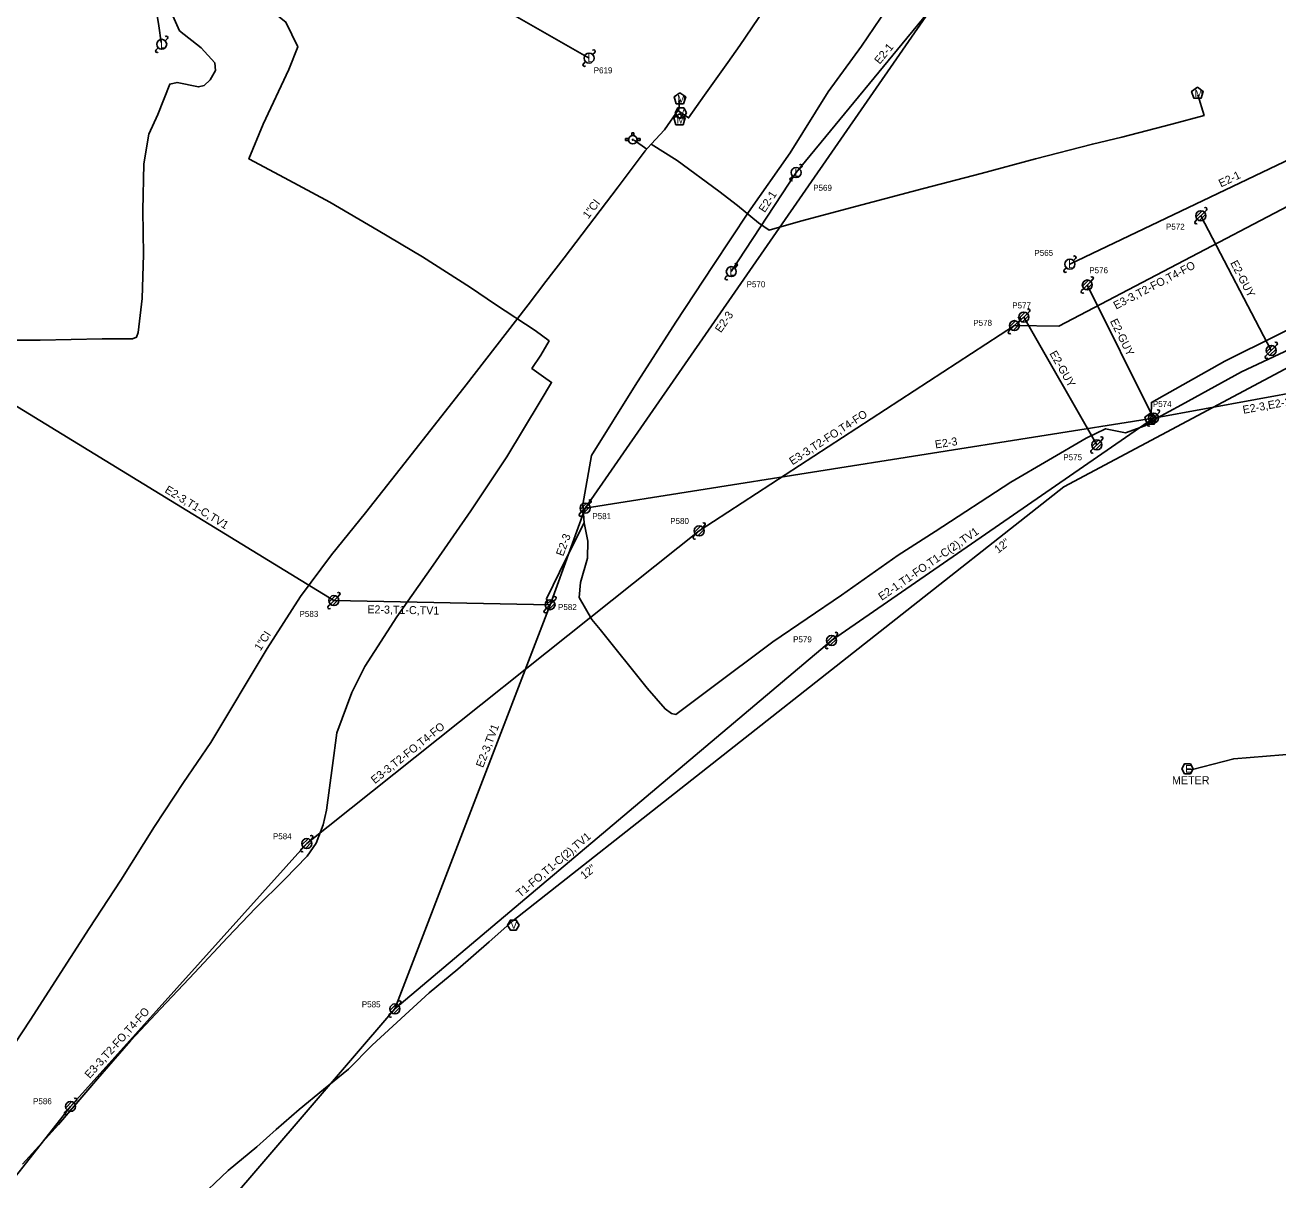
# Model space of a CAD drawing. Extents: x 1614474 to 1865144, y 1098877 to 1212550.
# Drawn here: x 1812286 to 1812913, y 1189306 to 1189883 of the extents above; entities that cross this region are included whole.
import ezdxf

# ---------------------------------------------------------------- set-up
doc = ezdxf.new("R2010")
doc.units = 0
for name, color, linetype in [('RD_EX_SU_Elec', 7, 'Continuous'), ('RD_EX_SU_Gas', 7, 'Continuous'), ('RD_EX_SU_H2O', 7, 'Continuous'), ('RD_EX_SU_Ovhd', 7, 'Continuous'), ('RD_EX_SU_Pole', 7, 'Continuous'), ('RD_EX_SU_Telecom', 7, 'Continuous'), ('RD_EX_SU_TX_Elec', 7, 'Continuous'), ('RD_EX_SU_TX_H2O', 7, 'Continuous'), ('RD_EX_SU_TX_Pole', 7, 'Continuous')]:
    doc.layers.add(name, color=color, linetype=linetype)

# ---------------------------------------------------------------- blocks, each defined once
blk = doc.blocks.new('SUE_PP')
at = {"layer": 'RD_EX_SU_Pole'}
for p, q in [((-2.41, -0.65), (0.65, 2.41)), ((-1.77, -1.77), (1.77, 1.77)), ((-0.65, -2.41), (2.41, 0.65)), ((1.77, 1.77), (2.83, 2.83)), ((-2.83, -2.83), (-1.77, -1.77))]:
    blk.add_line(p, q, dxfattribs=at)
blk.add_circle((0, 0), 2.5, dxfattribs=at)
for centre, start, end in [((2.3, 3.36), 315, 135), ((-2.3, -3.36), 135, 315)]:
    blk.add_arc(centre, 0.75, start, end, dxfattribs=at)
blk = doc.blocks.new('SUE_WM')
at = {"layer": 'RD_EX_SU_H2O'}
blk.add_lwpolyline([(0, 3.05), (-2.9, 0.94), (-1.79, -2.47), (1.79, -2.47), (2.9, 0.94)], close=True, dxfattribs=at)
blk.add_text('M', height=3.75, dxfattribs=at).set_placement((-1.43, -1.88))
blk = doc.blocks.new('SUE_WFH')
at = {"layer": 'RD_EX_SU_H2O'}
for p, q in [((-2.01, 0.6), (-3.65, 0.6)), ((-3.65, 0.6), (-3.65, -0.45)), ((-0.48, 3.38), (-0.48, 2.04)), ((0.57, 3.38), (-0.48, 3.38)), ((0.57, 2.02), (0.57, 3.38)), ((3.7, 0.6), (2.01, 0.6)), ((3.7, -0.45), (3.7, 0.6)), ((-3.65, -0.45), (-2.05, -0.45)), ((2.05, -0.45), (3.7, -0.45))]:
    blk.add_line(p, q, dxfattribs=at)
for radius in [2.1, 0.263]:
    blk.add_circle((0, 0), radius, dxfattribs=at)
for start, end in [(163.3387, 192.31502), (74.24552, 103.21276), (347.68498, 16.6613)]:
    blk.add_arc((0, 0), 2.1, start, end, dxfattribs=at)
blk = doc.blocks.new('SUE_WV')
at = {"layer": 'RD_EX_SU_H2O'}
blk.add_lwpolyline([(2.89, 0), (1.44, 2.5), (-1.44, 2.5), (-2.89, 0), (-1.44, -2.5), (1.44, -2.5)], close=True, dxfattribs=at)
blk.add_text('V', height=3.75, dxfattribs=at).set_placement((-1.43, -1.88))
blk = doc.blocks.new('SUE_TPP')
at = {"layer": 'RD_EX_SU_Telecom'}
blk.add_lwpolyline([(0, 3), (-2.85, 0.93), (-1.76, -2.43), (1.76, -2.43), (2.85, 0.93)], close=True, dxfattribs=at)
blk.add_text('T', height=3.75, dxfattribs=at).set_placement((-1.25, -1.88))

msp = doc.modelspace()

# ---------------------------------------------------------------- linework, layer by layer
at = {"layer": 'RD_EX_SU_Elec'}
for points in [[(1812338.4, 1189919.65), (1812340.34, 1189916.59), (1812345.26, 1189909.46), (1812348.64, 1189901.91), (1812349.43, 1189899.03), (1812351.17, 1189895.4), (1812353.18, 1189882.82), (1812354.25, 1189874.6)], [(1812264.91, 1189727.31), (1812265.67, 1189726.04), (1812275.26, 1189725.72), (1812293.9, 1189725.79), (1812324.91, 1189726.47), (1812339.96, 1189726.45), (1812342, 1189727.19), (1812342.85, 1189729.51), (1812344.8, 1189746.63), (1812345.47, 1189768.56), (1812345.08, 1189790.52), (1812345.62, 1189813.9), (1812348.11, 1189828.63), (1812352.6, 1189838.52), (1812358.64, 1189853.73), (1812362.26, 1189854.61), (1812373.02, 1189852.36), (1812375.77, 1189853.01), (1812378.77, 1189855.94), (1812381.54, 1189860.45), (1812381.16, 1189864.31), (1812374.37, 1189871.78), (1812363.55, 1189880.36), (1812360.11, 1189887.91)], [(1812867.17, 1189511.33), (1812869.82, 1189511.09), (1812890.43, 1189516.51), (1812931.39, 1189519.83), (1812948.66, 1189519.83), (1812977.88, 1189518.89), (1813012.86, 1189516.32), (1813041.01, 1189513.73), (1813054.44, 1189512.83)]]:
    msp.add_lwpolyline(points, dxfattribs=at)
msp.add_lwpolyline([(1812870.21, 1189511.54), (1812868.76, 1189514.04), (1812865.88, 1189514.04), (1812864.43, 1189511.54), (1812865.88, 1189509.04), (1812868.76, 1189509.04)], close=True, dxfattribs=at)
at = {"layer": 'RD_EX_SU_Gas'}
for points in [[(1812350.56, 1189925.11), (1812355.45, 1189921.5), (1812366.81, 1189915.4), (1812382.49, 1189907.75), (1812405.3, 1189893.62), (1812416.71, 1189884.71), (1812422.6, 1189872.36), (1812418.09, 1189860.95), (1812405.32, 1189833.64), (1812398.17, 1189816.37), (1812415.89, 1189806.88), (1812438.68, 1189794.8), (1812462.87, 1189780.56), (1812484.99, 1189767.43), (1812508.94, 1189752.14), (1812521.5, 1189743.51)], [(1812284.99, 1189313.9), (1812303.01, 1189333.69), (1812322.46, 1189356.59), (1812338.97, 1189375.53), (1812354.15, 1189391.76), (1812371.04, 1189409.6), (1812387.56, 1189427.15), (1812401.7, 1189441.99), (1812416.18, 1189456.34), (1812427.37, 1189467.82), (1812431.84, 1189474.39), (1812435.26, 1189483.53), (1812436.89, 1189490.92), (1812440.02, 1189513.11), (1812442.18, 1189529.43), (1812449.6, 1189549.74), (1812456.14, 1189562.68), (1812472.17, 1189587.42), (1812490.28, 1189613.22), (1812509.04, 1189640.47), (1812527.08, 1189667.45), (1812543.81, 1189695.03), (1812549.46, 1189704.67), (1812545.37, 1189707.44), (1812539.64, 1189711.63), (1812544.17, 1189718.24), (1812548.26, 1189725.38), (1812541.31, 1189730.63), (1812521.5, 1189743.51)]]:
    msp.add_lwpolyline(points, dxfattribs=at)
at = {"layer": 'RD_EX_SU_H2O'}
for p, q in [((1812613.65, 1189836.35), (1812615.15, 1189838.7)), ((1812590.74, 1189825.76), (1812597.01, 1189821.14))]:
    msp.add_line(p, q, dxfattribs=at)
for points in [[(1812612.56, 1189840.5), (1812617.95, 1189836.82), (1812625.87, 1189848.13), (1812637.64, 1189864.59), (1812643.52, 1189872.99), (1812662.22, 1189900.64), (1812675.78, 1189920.39), (1812680.75, 1189927.9), (1812683.12, 1189931.82), (1812693.09, 1189946.35), (1812710.48, 1189971.74), (1812726.44, 1189995.92), (1812734.38, 1190007.07), (1812745.59, 1190023.32), (1812751.75, 1190022.25), (1812790.61, 1190014.84)], [(1812365.47, 1189504.6), (1812379.19, 1189524.75), (1812407.29, 1189571.67), (1812423.91, 1189597.62), (1812439.41, 1189618.47), (1812456.38, 1189639.41), (1812473.79, 1189661.44), (1812505.53, 1189701.88), (1812537.71, 1189743.34), (1812546.54, 1189755.06), (1812555.74, 1189766.91), (1812582.74, 1189802.46), (1812596.33, 1189820.43), (1812599.27, 1189823.76), (1812612.17, 1189815.55), (1812633.13, 1189800.29), (1812642.47, 1189793.08), (1812652.97, 1189784.33), (1812658.19, 1189780.71), (1812673.92, 1189785.16), (1812704.56, 1189793.37), (1812735.45, 1189801.49), (1812764.2, 1189809.12), (1812791.38, 1189816.46), (1812819.76, 1189823.73), (1812834.53, 1189827.25), (1812859.56, 1189833.75), (1812875.61, 1189838.08), (1812872.48, 1189848.39)], [(1812599.27, 1189823.76), (1812605.98, 1189830.95), (1812613.1, 1189841.28), (1812613.51, 1189845.79)], [(1812530.07, 1189435.57), (1812805.53, 1189652.49), (1812993.01, 1189752.31), (1813006.84, 1189768.49), (1813049.93, 1189785.18)], [(1812215.37, 1189273.71), (1812231.38, 1189297.27), (1812246.82, 1189320), (1812260.07, 1189340.98), (1812273.78, 1189363.08), (1812288.8, 1189385.82), (1812318.34, 1189431.67), (1812334.09, 1189455.86), (1812351.06, 1189482.68), (1812365.47, 1189504.6)], [(1812285.67, 1189190.08), (1812291.92, 1189198.39), (1812293.42, 1189200.99), (1812295.04, 1189203.2), (1812298.15, 1189207.91), (1812306.94, 1189219.23), (1812314.19, 1189228.24), (1812330.95, 1189248.47), (1812342.77, 1189262.48), (1812344.04, 1189264.17), (1812356.44, 1189279.47), (1812371.36, 1189295.14), (1812387.82, 1189310.78), (1812402.13, 1189322.66), (1812411.8, 1189331.2), (1812423.35, 1189341.32), (1812435.42, 1189351.21), (1812447.92, 1189361.34), (1812459.79, 1189373.47), (1812476.32, 1189388.52), (1812488.2, 1189399.48), (1812502.59, 1189411.4), (1812518.31, 1189425), (1812530.07, 1189435.57)]]:
    msp.add_lwpolyline(points, dxfattribs=at)
at = {"layer": 'RD_EX_SU_Ovhd'}
for p, q in [((1812493.92, 1189909.3), (1812568.21, 1189866.72)), ((1812566.25, 1189641.8), (1812739.55, 1189891.88)), ((1812671.68, 1189809.5), (1812739.55, 1189891.88)), ((1812808.56, 1189763.74), (1812982.29, 1189846.79)), ((1812639.29, 1189760.01), (1812671.68, 1189809.5)), ((1812873.98, 1189787.93), (1812909.18, 1189720.64)), ((1812817.25, 1189753.33), (1812850.33, 1189686.85)), ((1812785.52, 1189737.27), (1812822.02, 1189673.39)), ((1812623.25, 1189630.42), (1812780.79, 1189733.02)), ((1812850.33, 1189686.85), (1813029.22, 1189719.4)), ((1812267.77, 1189701.43), (1812440.67, 1189595.6)), ((1812566.25, 1189641.8), (1812850.33, 1189686.85)), ((1812689.41, 1189575.65), (1812850.33, 1189686.85)), ((1812548.7, 1189593.54), (1812566.25, 1189641.8)), ((1812427.11, 1189474.14), (1812623.25, 1189630.42)), ((1812440.67, 1189595.6), (1812548.7, 1189593.54)), ((1812471.17, 1189391.5), (1812548.7, 1189593.54)), ((1812471.17, 1189391.5), (1812689.41, 1189575.65)), ((1812309.05, 1189342.79), (1812427.11, 1189474.14)), ((1812308.36, 1189202.14), (1812471.17, 1189391.5)), ((1812196.69, 1189200.73), (1812309.05, 1189342.79))]:
    msp.add_line(p, q, dxfattribs=at)
msp.add_lwpolyline([(1812780.79, 1189733.02), (1812803.04, 1189732.83), (1812921.31, 1189794.68), (1812930.87, 1189813.64)], dxfattribs=at)
at = {"layer": 'RD_EX_SU_Pole'}
for p, q in [((1812356.37, 1189875.39), (1812357.43, 1189876.45)), ((1812351.77, 1189870.79), (1812352.83, 1189871.85)), ((1812569.98, 1189868.49), (1812571.04, 1189869.55)), ((1812565.38, 1189863.89), (1812566.44, 1189864.95)), ((1812673.44, 1189811.27), (1812674.5, 1189812.33)), ((1812668.85, 1189806.67), (1812669.91, 1189807.73)), ((1812871.57, 1189787.28), (1812874.63, 1189790.35)), ((1812872.22, 1189786.16), (1812875.75, 1189789.7)), ((1812873.34, 1189785.52), (1812876.4, 1189788.58)), ((1812875.75, 1189789.7), (1812876.81, 1189790.76)), ((1812871.16, 1189785.1), (1812872.22, 1189786.16)), ((1812641.05, 1189761.78), (1812642.11, 1189762.84)), ((1812805.73, 1189760.92), (1812806.79, 1189761.98)), ((1812810.33, 1189765.51), (1812811.39, 1189766.57)), ((1812636.46, 1189757.18), (1812637.52, 1189758.24)), ((1812814.83, 1189752.68), (1812817.9, 1189755.75)), ((1812819.02, 1189755.1), (1812820.08, 1189756.16)), ((1812814.42, 1189750.5), (1812815.48, 1189751.56)), ((1812815.48, 1189751.56), (1812819.02, 1189755.1)), ((1812816.6, 1189750.92), (1812819.66, 1189753.98)), ((1812783.1, 1189736.62), (1812786.16, 1189739.68)), ((1812783.75, 1189735.5), (1812787.29, 1189739.04)), ((1812784.87, 1189734.86), (1812787.93, 1189737.92)), ((1812787.29, 1189739.04), (1812788.35, 1189740.1)), ((1812777.96, 1189730.19), (1812779.02, 1189731.25)), ((1812778.37, 1189732.37), (1812781.43, 1189735.43)), ((1812779.02, 1189731.25), (1812782.56, 1189734.79)), ((1812780.14, 1189730.6), (1812783.2, 1189733.66)), ((1812782.56, 1189734.79), (1812783.62, 1189735.85)), ((1812782.69, 1189734.44), (1812783.75, 1189735.5)), ((1812906.35, 1189717.82), (1812907.41, 1189718.88)), ((1812906.76, 1189720), (1812909.82, 1189723.06)), ((1812907.41, 1189718.88), (1812910.95, 1189722.41)), ((1812908.53, 1189718.23), (1812911.59, 1189721.29)), ((1812910.95, 1189722.41), (1812912.01, 1189723.47)), ((1812847.92, 1189686.2), (1812850.98, 1189689.26)), ((1812848.57, 1189685.08), (1812852.1, 1189688.62)), ((1812849.69, 1189684.43), (1812852.75, 1189687.49)), ((1812852.1, 1189688.62), (1812853.16, 1189689.68)), ((1812847.5, 1189684.02), (1812848.57, 1189685.08)), ((1812819.6, 1189672.74), (1812822.67, 1189675.81)), ((1812820.25, 1189671.62), (1812823.79, 1189675.16)), ((1812821.37, 1189670.98), (1812824.43, 1189674.04)), ((1812823.79, 1189675.16), (1812824.85, 1189676.22)), ((1812819.19, 1189670.56), (1812820.25, 1189671.62)), ((1812563.84, 1189641.16), (1812566.9, 1189644.22)), ((1812564.48, 1189640.04), (1812568.02, 1189643.57)), ((1812568.02, 1189643.57), (1812569.08, 1189644.63)), ((1812563.42, 1189638.98), (1812564.48, 1189640.04)), ((1812565.6, 1189639.39), (1812568.66, 1189642.45)), ((1812620.84, 1189629.77), (1812623.9, 1189632.84)), ((1812621.48, 1189628.65), (1812625.02, 1189632.19)), ((1812622.6, 1189628.01), (1812625.67, 1189631.07)), ((1812625.02, 1189632.19), (1812626.08, 1189633.25)), ((1812620.42, 1189627.59), (1812621.48, 1189628.65)), ((1812437.84, 1189592.77), (1812438.9, 1189593.84)), ((1812438.26, 1189594.96), (1812441.32, 1189598.02)), ((1812438.9, 1189593.84), (1812442.44, 1189597.37)), ((1812440.02, 1189593.19), (1812443.08, 1189596.25)), ((1812442.44, 1189597.37), (1812443.5, 1189598.43)), ((1812686.58, 1189572.82), (1812687.64, 1189573.88)), ((1812686.99, 1189575), (1812690.05, 1189578.06)), ((1812687.64, 1189573.88), (1812691.17, 1189577.42)), ((1812688.76, 1189573.24), (1812691.82, 1189576.3)), ((1812691.17, 1189577.42), (1812692.24, 1189578.48)), ((1812424.69, 1189473.49), (1812427.75, 1189476.55)), ((1812425.34, 1189472.37), (1812428.87, 1189475.91)), ((1812426.46, 1189471.72), (1812429.52, 1189474.79)), ((1812428.87, 1189475.91), (1812429.93, 1189476.97)), ((1812424.28, 1189471.31), (1812425.34, 1189472.37)), ((1812468.76, 1189390.86), (1812471.82, 1189393.92)), ((1812469.41, 1189389.74), (1812472.94, 1189393.27)), ((1812472.94, 1189393.27), (1812474, 1189394.33)), ((1812468.35, 1189388.67), (1812469.41, 1189389.74)), ((1812470.53, 1189389.09), (1812473.59, 1189392.15)), ((1812306.63, 1189342.15), (1812309.7, 1189345.21)), ((1812307.28, 1189341.03), (1812310.82, 1189344.56)), ((1812308.4, 1189340.38), (1812311.46, 1189343.44)), ((1812310.82, 1189344.56), (1812311.88, 1189345.62)), ((1812306.22, 1189339.96), (1812307.28, 1189341.03))]:
    msp.add_line(p, q, dxfattribs=at)
for centre in [(1812354.6, 1189873.62), (1812568.21, 1189866.72), (1812671.68, 1189809.5), (1812873.98, 1189787.93), (1812639.29, 1189760.01), (1812808.56, 1189763.74), (1812817.25, 1189753.33), (1812785.52, 1189737.27), (1812780.79, 1189733.02), (1812909.18, 1189720.64), (1812850.33, 1189686.85), (1812822.02, 1189673.39), (1812566.25, 1189641.8), (1812623.25, 1189630.42), (1812440.67, 1189595.6), (1812689.41, 1189575.65), (1812427.11, 1189474.14), (1812471.17, 1189391.5), (1812309.05, 1189342.79)]:
    msp.add_circle(centre, 2.5, dxfattribs=at)
for centre, start, end in [((1812356.9, 1189876.98), 315, 135), ((1812352.3, 1189870.26), 135, 315), ((1812570.51, 1189870.08), 315, 135), ((1812565.91, 1189863.36), 135, 315), ((1812673.97, 1189812.86), 315, 135), ((1812669.38, 1189806.14), 135, 315), ((1812876.28, 1189791.29), 315, 135), ((1812871.69, 1189784.57), 135, 315), ((1812641.58, 1189763.37), 315, 135), ((1812810.86, 1189767.1), 315, 135), ((1812636.99, 1189756.65), 135, 315), ((1812806.26, 1189760.39), 135, 315), ((1812819.55, 1189756.69), 315, 135), ((1812814.95, 1189749.97), 135, 315), ((1812783.09, 1189736.38), 315, 135), ((1812787.82, 1189740.63), 315, 135), ((1812783.22, 1189733.91), 135, 315), ((1812778.49, 1189729.66), 135, 315), ((1812911.48, 1189724), 315, 135), ((1812906.88, 1189717.28), 135, 315), ((1812852.63, 1189690.21), 315, 135), ((1812848.04, 1189683.49), 135, 315), ((1812824.32, 1189676.75), 315, 135), ((1812819.72, 1189670.03), 135, 315), ((1812568.55, 1189645.16), 315, 135), ((1812563.95, 1189638.45), 135, 315), ((1812625.55, 1189633.78), 315, 135), ((1812620.95, 1189627.06), 135, 315), ((1812442.97, 1189598.96), 315, 135), ((1812438.37, 1189592.24), 135, 315), ((1812691.7, 1189579.01), 315, 135), ((1812687.11, 1189572.29), 135, 315), ((1812429.4, 1189477.5), 315, 135), ((1812424.81, 1189470.78), 135, 315), ((1812473.47, 1189394.86), 315, 135), ((1812468.88, 1189388.14), 135, 315), ((1812311.35, 1189346.15), 315, 135), ((1812306.75, 1189339.43), 135, 315)]:
    msp.add_arc(centre, 0.75, start, end, dxfattribs=at)
at = {"layer": 'RD_EX_SU_Telecom'}
msp.add_line((1812848.97, 1189686.04), (1812849.53, 1189686.19), dxfattribs=at)
for points in [[(1812547.59, 1189594.15), (1812546.89, 1189596.39), (1812556.68, 1189616.67), (1812565.68, 1189634.43), (1812565.02, 1189643.57), (1812569.34, 1189668.06), (1812591.18, 1189703.15), (1812611.52, 1189734.81), (1812630.22, 1189763.12), (1812647.89, 1189789.79), (1812668.66, 1189819.44), (1812687.76, 1189849.8), (1812704.38, 1189872.74), (1812723.32, 1189900.86)], [(1812849.23, 1189687.67), (1812849.3, 1189694.68), (1812885.98, 1189715.21), (1812939.04, 1189741.55), (1812976.77, 1189759.12), (1812980.75, 1189758.26), (1812983.89, 1189753.32)], [(1812565.68, 1189634.43), (1812567.54, 1189625.36), (1812567.39, 1189616.72), (1812563.96, 1189604.67), (1812563.19, 1189597.08), (1812569.61, 1189586.2), (1812573.75, 1189581.1), (1812597.26, 1189551.83), (1812606.19, 1189541.48), (1812609.41, 1189539.24), (1812611.54, 1189538.74), (1812628.22, 1189551.08), (1812659.99, 1189574.9), (1812694.4, 1189598.34), (1812722.68, 1189618.36), (1812741.27, 1189630.12), (1812778.99, 1189654.82), (1812816.76, 1189676.77), (1812826.41, 1189681.49), (1812836.36, 1189679.38), (1812845.96, 1189682.94), (1812852.02, 1189686.77), (1812864.3, 1189693.51), (1812894.35, 1189709.92), (1812926.56, 1189725.13)]]:
    msp.add_lwpolyline(points, dxfattribs=at)

# ---------------------------------------------------------------- block references
at = {"layer": 'RD_EX_SU_H2O'}
for name, p in [('SUE_WM', (1812613.61, 1189846.35)), ('SUE_WM', (1812872.29, 1189849.13)), ('SUE_WM', (1812613.41, 1189835.9)), ('SUE_WV', (1812614.07, 1189839.38)), ('SUE_WFH', (1812590.08, 1189825.92)), ('SUE_WV', (1812530.33, 1189433.43))]:
    msp.add_blockref(name, p, dxfattribs=at)
at = {"layer": 'RD_EX_SU_Pole'}
msp.add_blockref('SUE_PP', (1812548.7, 1189593.54), dxfattribs=at)
at = {"layer": 'RD_EX_SU_Telecom'}
msp.add_blockref('SUE_TPP', (1812848.91, 1189686.28), dxfattribs=at)

# ---------------------------------------------------------------- texts
at = {"layer": 'RD_EX_SU_Elec'}
msp.add_text('E', height=3.75, dxfattribs=at).set_placement((1812866.16, 1189509.67))
at = {"layer": 'RD_EX_SU_Ovhd'}
for s, rotation, p in [('E2-1', 50.51516, (1812713.47, 1189863.37)), ('E2-1', 25.55008, (1812884.06, 1189802.05)), ('E2-1', 56.79586, (1812656.01, 1189789.22)), ('E3-3,T2-FO,T4-FO', 27.60896, (1812831.61, 1189741)), ('E2-GUY', 297.61131, (1812888.57, 1189764.37)), ('E2-3', 55.27883, (1812634.08, 1189729.15)), ('E2-GUY', 296.45574, (1812828.49, 1189735.24)), ('E2-GUY', 299.74399, (1812798.21, 1189719.09)), ('E2-3,E2-1,TV1,T1-C,T1-FO', 10.31357, (1812895.31, 1189688.93)), ('E3-3,T2-FO,T4-FO', 33.07439, (1812669.86, 1189663.16)), ('E2-3', 9.00961, (1812741.41, 1189671.6)), ('E2-3,T1-C,TV1', 328.53096, (1812355.77, 1189649.91)), ('E2-1,T1-FO,T1-C(2),TV1', 34.64392, (1812714.51, 1189595.43)), ('E2-3', 70.01725, (1812555.28, 1189617.49)), ('E2-3,T1-C,TV1', 358.90862, (1812457.35, 1189589.28)), ('E3-3,T2-FO,T4-FO', 38.54664, (1812461.14, 1189503.81)), ('E2-3,TV1', 69.00738, (1812515.2, 1189511.81)), ('T1-FO,T1-C(2),TV1', 40.1581, (1812533.84, 1189446.99)), ('E3-3,T2-FO,T4-FO', 48.05019, (1812318.62, 1189356.44))]:
    msp.add_text(s, height=4, rotation=rotation, dxfattribs=at).set_placement(p)
at = {"layer": 'RD_EX_SU_Pole'}
for p in [(1812353.74, 1189871.62), (1812567.35, 1189864.72), (1812670.81, 1189807.5), (1812638.42, 1189758.01), (1812807.7, 1189761.74)]:
    msp.add_text('L', height=4, dxfattribs=at).set_placement(p)
at = {"layer": 'RD_EX_SU_TX_Elec'}
msp.add_text('METER', height=4, dxfattribs=at).set_placement((1812859.59, 1189503.84))
at = {"layer": 'RD_EX_SU_TX_H2O'}
for s, rotation, p in [('1"CI', 52.78072, (1812567.82, 1189786.12)), ('12"', 38.22084, (1812772.71, 1189619.01)), ('1"CI', 57.36837, (1812403.94, 1189570.14)), ('12"', 38.22084, (1812565.81, 1189456.07))]:
    msp.add_text(s, height=4, rotation=rotation, dxfattribs=at).set_placement(p)
at = {"layer": 'RD_EX_SU_TX_Pole'}
for s, p in [('P619', (1812570.52, 1189859.11)), ('P569', (1812680.23, 1189800.4)), ('P572', (1812856.56, 1189780.98)), ('P565', (1812790.79, 1189767.89)), ('P576', (1812818.23, 1189759.2)), ('P570', (1812646.95, 1189752.18)), ('P577', (1812779.7, 1189741.62)), ('P578', (1812760.25, 1189732.91)), ('P574', (1812850.01, 1189692.37)), ('P575', (1812805.25, 1189665.73)), ('P581', (1812569.85, 1189636.29)), ('P580', (1812608.75, 1189633.88)), ('P582', (1812552.69, 1189590.86)), ('P583', (1812423.49, 1189587.44)), ('P579', (1812670.19, 1189574.72)), ('P584', (1812410.18, 1189476.3)), ('P585', (1812454.62, 1189392.3)), ('P586', (1812290.28, 1189343.89))]:
    msp.add_text(s, height=3, dxfattribs=at).set_placement(p)

doc.saveas('drawing.dxf')
